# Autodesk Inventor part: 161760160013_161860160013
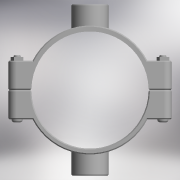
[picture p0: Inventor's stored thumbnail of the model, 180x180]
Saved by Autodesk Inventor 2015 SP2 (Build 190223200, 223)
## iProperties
Created: 2017-05
Part Number: 161760160013_161860160013
Material: Generic
Description: PLASSON DOUBLE SADDLE 1601.1/4"
Document SubType Name: Modeling
Designer: KIM
Density: 1 g/cm^3
Appearance: Default
Author: KIM
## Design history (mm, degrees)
derived "16176.ipt"
feature "Solid1::16176.ipt"
feature "Solid2::16176.ipt"
tag "TaggingFeature1"
body "Solid1"
body "Solid2"
other parameters: "d0" = 176, "d1" = 223, "d4" = 145, "d5" = 0, "d6" = 11.15, "d7" = 223, "d8" = 0.1, "d10" = 0, "d11" = 1.6, "d20" = 1.6, "d23" = 1.6, "d36" = 15, "d37" = 12, "d38" = 88, "d39" = 0, "d40" = 3, "d41" = 5, "d42" = 0, "d44" = 3, "d45" = 0, "d46" = 1.6, "d52" = 38.952, "d53" = 25, "d54" = 0, "d55" = 32, "d57" = 0, "d58" = 172.8, "d60" = 0, "d62" = 15, "d63" = 12, "d66" = 121, "d67" = 234, "d68" = 50.6376, "d69" = 38.952, "d70" = 25, "d71" = 0, "d72" = 32, "d74" = 0, "d75" = 1.6, "B_" = 32, "G_" = 38.952, "A_" = 117, "L_" = 223, "L_1" = 145, "l_2" = 25
